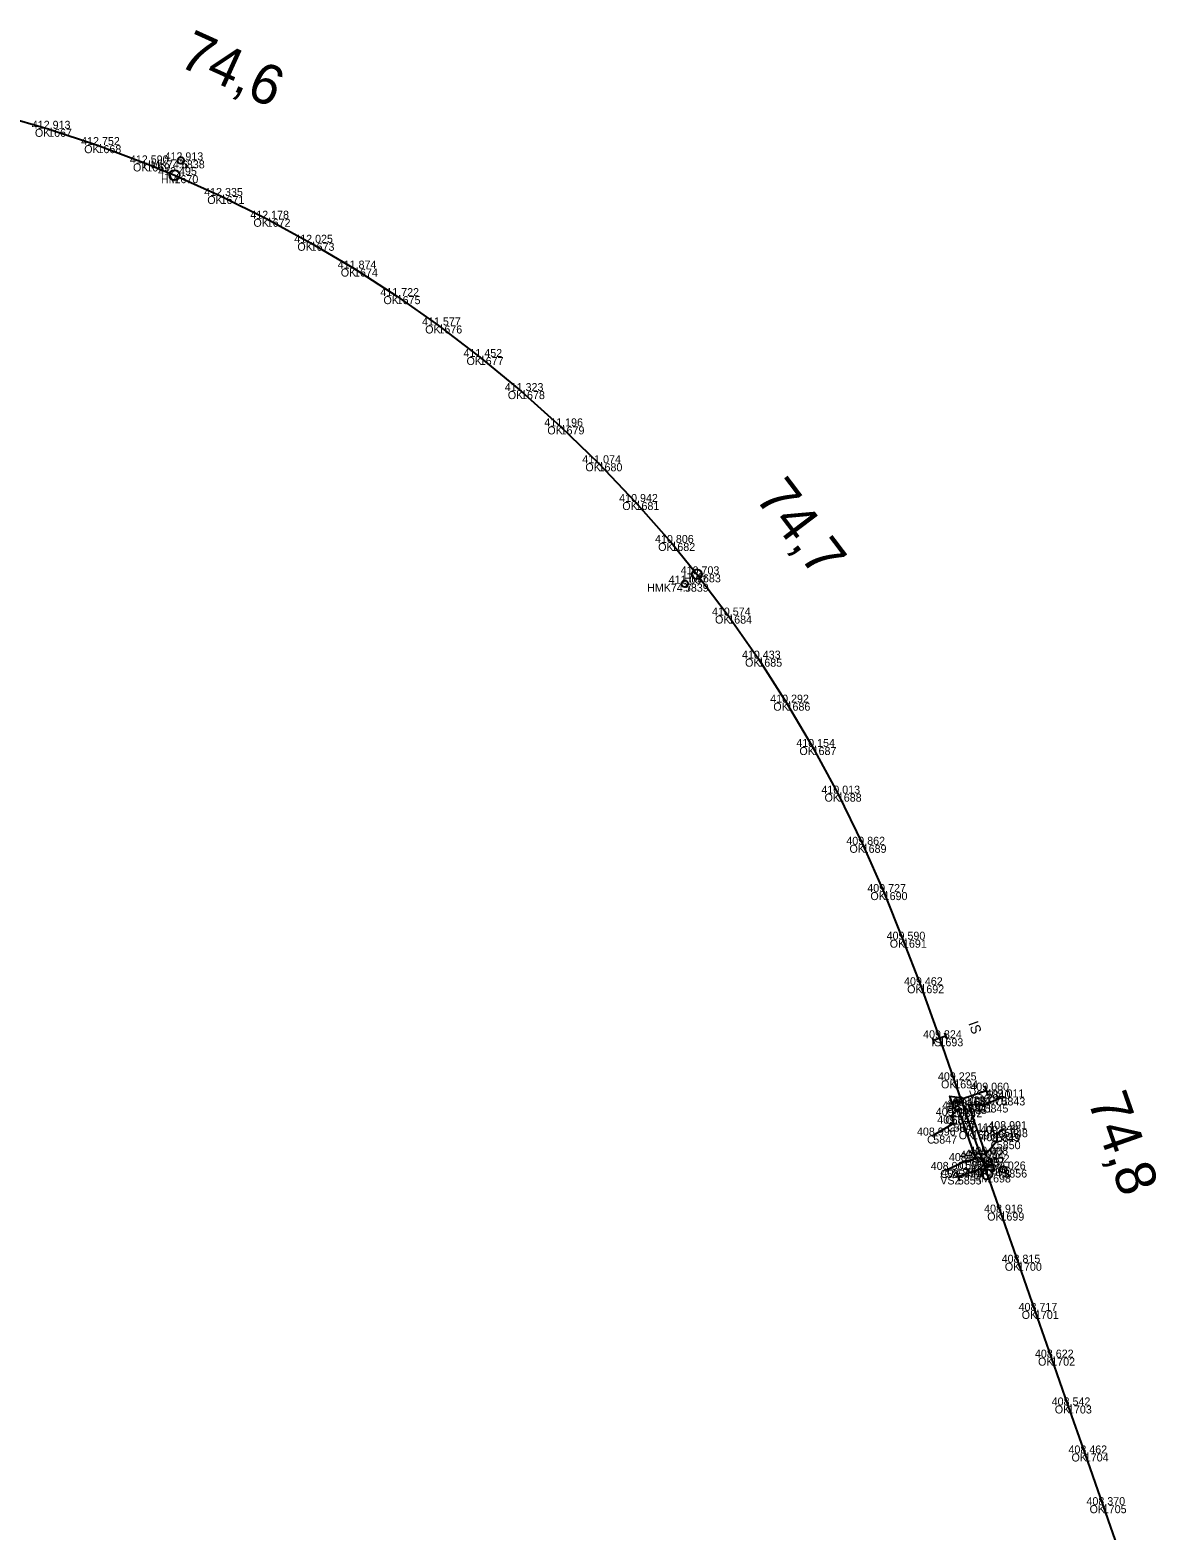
# Model space of a CAD drawing. Extents: x -621782 to -610392, y -1141853 to -1122321.
# Drawn here: x -619167.3 to -618998.3, y -1130303.7 to -1130078.8 of the extents above; entities that cross this region are included whole.
import ezdxf

# ---------------------------------------------------------------- set-up
doc = ezdxf.new("R2010")
doc.units = 0
for name, color, linetype in [('Vrstva 1', 7, 'Continuous'), ('Vrstva 3', 7, 'Continuous'), ('Vrstva 4', 7, 'Continuous'), ('Vrstva 51', 7, 'Continuous'), ('Vrstva 60', 7, 'Continuous'), ('Vrstva 61', 7, 'Continuous'), ('Vrstva 62', 7, 'Continuous'), ('Vrstva 7', 7, 'Continuous')]:
    doc.layers.add(name, color=color, linetype=linetype)

msp = doc.modelspace()

# ---------------------------------------------------------------- linework, layer by layer
at = {"layer": 'Vrstva 1'}
msp.add_lwpolyline([(-619171.08, -1130091.68), (-619164.55, -1130093.59), (-619157.15, -1130096.03), (-619149.84, -1130098.78), (-619145.6, -1130100.54), (-619138.69, -1130103.66), (-619131.77, -1130107.08), (-619125.18, -1130110.68), (-619118.67, -1130114.55), (-619112.28, -1130118.68), (-619106.02, -1130123.08), (-619099.82, -1130127.81), (-619093.62, -1130132.92), (-619087.69, -1130138.21), (-619082, -1130143.74), (-619076.46, -1130149.55), (-619071.08, -1130155.69), (-619067.24, -1130160.39), (-619062.55, -1130166.58), (-619058.04, -1130173.04), (-619053.81, -1130179.64), (-619049.9, -1130186.28), (-619046.12, -1130193.28), (-619042.39, -1130200.95), (-619039.24, -1130208.04), (-619036.35, -1130215.18), (-619033.74, -1130222.01), (-619030.88, -1130229.96), (-619028.66, -1130236.27), (-619027.33, -1130240.12), (-619026.01, -1130243.9), (-619024.61, -1130247.86), (-619023.73, -1130250.38), (-619021.73, -1130256.1), (-619019.09, -1130263.62), (-619016.56, -1130270.84), (-619014.11, -1130277.85), (-619011.6, -1130285.02), (-619009.08, -1130292.22), (-619006.38, -1130299.97), (-619003.78, -1130307.42)], dxfattribs=at)
at = {"layer": 'Vrstva 3'}
for p, q in [((-619030.11, -1130229.15), (-619029.77, -1130230.09)), ((-619031.99, -1130229.82), (-619031.65, -1130230.77)), ((-619029.94, -1130229.62), (-619031.82, -1130230.3))]:
    msp.add_line(p, q, dxfattribs=at)
at = {"layer": 'Vrstva 4'}
for p, q in [((-619023.55, -1130238.56), (-619024.05, -1130237.09)), ((-619028.15, -1130239.54), (-619028.58, -1130239.32)), ((-619023.78, -1130248.94), (-619023.34, -1130249.15)), ((-619028.37, -1130249.94), (-619027.86, -1130251.41))]:
    msp.add_line(p, q, dxfattribs=at)
for points in [[(-619023.8, -1130237.82), (-619027.09, -1130238.96), (-619028.66, -1130240.54), (-619029.32, -1130238.66), (-619027.09, -1130238.96)], [(-619027.33, -1130240.12), (-619026.01, -1130243.9), (-619024.61, -1130247.86)], [(-619028.12, -1130250.68), (-619024.83, -1130249.53), (-619023.27, -1130247.93), (-619022.6, -1130249.82), (-619024.83, -1130249.53)]]:
    msp.add_lwpolyline(points, dxfattribs=at)
for centre in [(-619028.36, -1130239.43), (-619023.56, -1130249.05)]:
    msp.add_circle(centre, 0.248, dxfattribs=at)
at = {"layer": 'Vrstva 51'}
for points in [[(-619029.82, -1130249.7), (-619027.01, -1130248.38), (-619025.42, -1130248.01), (-619028.02, -1130240.61), (-619029.07, -1130241.58), (-619028.76, -1130242.76), (-619031.8, -1130244.55)], [(-619021.19, -1130243.59), (-619022.32, -1130244.28), (-619022.28, -1130245.39), (-619023.94, -1130247.41), (-619026.54, -1130239.87), (-619024.11, -1130239.89), (-619021.58, -1130238.83)]]:
    msp.add_lwpolyline(points, dxfattribs=at)
at = {"layer": 'Vrstva 60'}
for p, q in [((-619164.55, -1130093.59), (-619164.55, -1130093.59)), ((-619157.15, -1130096.03), (-619157.15, -1130096.03)), ((-619149.84, -1130098.78), (-619149.84, -1130098.78)), ((-619144.64, -1130098.32), (-619144.64, -1130098.32)), ((-619145.6, -1130100.54), (-619145.6, -1130100.54)), ((-619138.69, -1130103.66), (-619138.69, -1130103.66)), ((-619131.77, -1130107.08), (-619131.77, -1130107.08)), ((-619125.18, -1130110.68), (-619125.18, -1130110.68)), ((-619118.67, -1130114.55), (-619118.67, -1130114.55)), ((-619112.28, -1130118.68), (-619112.28, -1130118.68)), ((-619106.02, -1130123.08), (-619106.02, -1130123.08)), ((-619099.82, -1130127.81), (-619099.82, -1130127.81)), ((-619093.62, -1130132.92), (-619093.62, -1130132.92)), ((-619087.69, -1130138.21), (-619087.69, -1130138.21)), ((-619082, -1130143.74), (-619082, -1130143.74)), ((-619076.46, -1130149.55), (-619076.46, -1130149.55)), ((-619071.08, -1130155.69), (-619071.08, -1130155.69)), ((-619069.05, -1130161.8), (-619069.05, -1130161.8)), ((-619067.24, -1130160.39), (-619067.24, -1130160.39)), ((-619062.55, -1130166.58), (-619062.55, -1130166.58)), ((-619058.04, -1130173.04), (-619058.04, -1130173.04)), ((-619053.81, -1130179.64), (-619053.81, -1130179.64)), ((-619049.9, -1130186.28), (-619049.9, -1130186.28)), ((-619046.12, -1130193.28), (-619046.12, -1130193.28)), ((-619042.39, -1130200.95), (-619042.39, -1130200.95)), ((-619039.24, -1130208.04), (-619039.24, -1130208.04)), ((-619036.35, -1130215.18), (-619036.35, -1130215.18)), ((-619033.74, -1130222.01), (-619033.74, -1130222.01)), ((-619030.88, -1130229.96), (-619030.88, -1130229.96)), ((-619028.66, -1130236.27), (-619028.66, -1130236.27)), ((-619023.8, -1130237.82), (-619023.8, -1130237.82)), ((-619028.02, -1130240.61), (-619028.02, -1130240.61)), ((-619027.33, -1130240.12), (-619027.33, -1130240.12)), ((-619026.54, -1130239.87), (-619026.54, -1130239.87)), ((-619024.11, -1130239.89), (-619024.11, -1130239.89)), ((-619021.58, -1130238.83), (-619021.58, -1130238.83)), ((-619029.07, -1130241.58), (-619029.07, -1130241.58)), ((-619028.76, -1130242.76), (-619028.76, -1130242.76)), ((-619031.8, -1130244.55), (-619031.8, -1130244.55)), ((-619026.01, -1130243.9), (-619026.01, -1130243.9)), ((-619022.32, -1130244.28), (-619022.32, -1130244.28)), ((-619021.19, -1130243.59), (-619021.19, -1130243.59)), ((-619023.94, -1130247.41), (-619023.94, -1130247.41)), ((-619022.28, -1130245.39), (-619022.28, -1130245.39)), ((-619027.01, -1130248.38), (-619027.01, -1130248.38)), ((-619025.42, -1130248.01), (-619025.42, -1130248.01)), ((-619024.61, -1130247.86), (-619024.61, -1130247.86)), ((-619021.3, -1130249.64), (-619021.3, -1130249.64)), ((-619029.82, -1130249.7), (-619029.82, -1130249.7)), ((-619028.12, -1130250.68), (-619028.12, -1130250.68)), ((-619023.73, -1130250.38), (-619023.73, -1130250.38)), ((-619021.73, -1130256.1), (-619021.73, -1130256.1)), ((-619019.09, -1130263.62), (-619019.09, -1130263.62)), ((-619016.56, -1130270.84), (-619016.56, -1130270.84)), ((-619014.11, -1130277.85), (-619014.11, -1130277.85)), ((-619011.6, -1130285.02), (-619011.6, -1130285.02)), ((-619009.08, -1130292.22), (-619009.08, -1130292.22)), ((-619006.38, -1130299.97), (-619006.38, -1130299.97))]:
    msp.add_line(p, q, dxfattribs=at)
at = {"layer": 'Vrstva 7'}
for p, q in [((-619144.69, -1130098.3), (-619144.59, -1130098.34)), ((-619069.08, -1130161.76), (-619069.02, -1130161.84)), ((-619021.32, -1130249.6), (-619021.29, -1130249.69))]:
    msp.add_line(p, q, dxfattribs=at)
for centre, radius in [((-619144.64, -1130098.32), 0.5), ((-619145.6, -1130100.54), 0.75), ((-619067.24, -1130160.39), 0.75), ((-619069.05, -1130161.8), 0.5), ((-619023.73, -1130250.38), 0.75), ((-619021.3, -1130249.64), 0.5)]:
    msp.add_circle(centre, radius, dxfattribs=at)

# ---------------------------------------------------------------- texts
at = {"layer": 'Vrstva 3'}
msp.add_text('IS', height=1.5, rotation=289.7838, dxfattribs=at).set_placement((-619026.56, -1130227.7))
at = {"layer": 'Vrstva 60'}
for s, p in [('1667', (-619164.55, -1130094.79)), ('1668', (-619157.15, -1130097.24)), ('1669', (-619149.84, -1130099.98)), ('5838', (-619144.64, -1130099.52)), ('1670', (-619145.6, -1130101.74)), ('1671', (-619138.69, -1130104.86)), ('1672', (-619131.77, -1130108.28)), ('1673', (-619125.18, -1130111.88)), ('1674', (-619118.67, -1130115.75)), ('1675', (-619112.28, -1130119.88)), ('1676', (-619106.02, -1130124.28)), ('1677', (-619099.82, -1130129.01)), ('1678', (-619093.62, -1130134.12)), ('1679', (-619087.69, -1130139.41)), ('1680', (-619082, -1130144.94)), ('1681', (-619076.46, -1130150.75)), ('1682', (-619071.08, -1130156.89)), ('5839', (-619069.05, -1130163)), ('1683', (-619067.24, -1130161.59)), ('1684', (-619062.55, -1130167.78)), ('1685', (-619058.04, -1130174.24)), ('1686', (-619053.81, -1130180.84)), ('1687', (-619049.9, -1130187.49)), ('1688', (-619046.12, -1130194.48)), ('1689', (-619042.39, -1130202.15)), ('1690', (-619039.24, -1130209.24)), ('1691', (-619036.35, -1130216.38)), ('1692', (-619033.74, -1130223.21)), ('1693', (-619030.88, -1130231.16)), ('1694', (-619028.66, -1130237.47)), ('5840', (-619023.8, -1130239.02)), ('5842', (-619028.02, -1130241.81)), ('1695', (-619027.33, -1130241.32)), ('5841', (-619026.54, -1130241.07)), ('5845', (-619024.11, -1130241.09)), ('5843', (-619021.58, -1130240.03)), ('5844', (-619029.07, -1130242.78)), ('5846', (-619028.76, -1130243.96)), ('5847', (-619031.8, -1130245.75)), ('1696', (-619026.01, -1130245.1)), ('5849', (-619022.32, -1130245.48)), ('5848', (-619021.19, -1130244.79)), ('5852', (-619023.94, -1130248.6)), ('5850', (-619022.28, -1130246.59)), ('5851', (-619027.01, -1130249.58)), ('5853', (-619025.42, -1130249.21)), ('1697', (-619024.61, -1130249.06)), ('5856', (-619021.3, -1130250.84)), ('5854', (-619029.82, -1130250.9)), ('5855', (-619028.12, -1130251.88)), ('1698', (-619023.73, -1130251.58)), ('1699', (-619021.73, -1130257.3)), ('1700', (-619019.09, -1130264.82)), ('1701', (-619016.56, -1130272.04)), ('1702', (-619014.11, -1130279.05)), ('1703', (-619011.6, -1130286.22)), ('1704', (-619009.08, -1130293.42)), ('1705', (-619006.38, -1130301.17))]:
    msp.add_text(s, height=1.2, dxfattribs=at).set_placement(p)
at = {"layer": 'Vrstva 61'}
for s, p in [('412.913', (-619167, -1130093.59)), ('412.752', (-619159.6, -1130096.03)), ('412.590', (-619152.29, -1130098.78)), ('412.913', (-619147.09, -1130098.32)), ('412.495', (-619148.05, -1130100.54)), ('412.335', (-619141.15, -1130103.66)), ('412.178', (-619134.23, -1130107.08)), ('412.025', (-619127.64, -1130110.68)), ('411.874', (-619121.12, -1130114.55)), ('411.722', (-619114.73, -1130118.68)), ('411.577', (-619108.47, -1130123.08)), ('411.452', (-619102.26, -1130127.81)), ('411.323', (-619096.07, -1130132.92)), ('411.196', (-619090.14, -1130138.21)), ('411.074', (-619084.45, -1130143.74)), ('410.942', (-619078.91, -1130149.55)), ('410.806', (-619073.53, -1130155.69)), ('410.703', (-619069.69, -1130160.39)), ('411.057', (-619071.5, -1130161.8)), ('410.574', (-619065, -1130166.58)), ('410.433', (-619060.5, -1130173.04)), ('410.292', (-619056.26, -1130179.64)), ('410.154', (-619052.35, -1130186.28)), ('410.013', (-619048.58, -1130193.28)), ('409.862', (-619044.84, -1130200.95)), ('409.727', (-619041.7, -1130208.04)), ('409.590', (-619038.8, -1130215.18)), ('409.462', (-619036.19, -1130222.01)), ('409.324', (-619033.33, -1130229.96)), ('409.225', (-619031.11, -1130236.27)), ('409.060', (-619026.25, -1130237.82)), ('409.011', (-619023.94, -1130238.83)), ('409.001', (-619031.43, -1130241.58)), ('409.118', (-619030.47, -1130240.61)), ('409.168', (-619029.78, -1130240.12)), ('409.134', (-619028.99, -1130239.87)), ('409.070', (-619026.57, -1130239.89)), ('409.056', (-619031.21, -1130242.76)), ('409.111', (-619028.36, -1130243.9)), ('408.991', (-619023.55, -1130243.59)), ('408.996', (-619034.25, -1130244.55)), ('409.038', (-619024.77, -1130244.28)), ('409.033', (-619024.73, -1130245.39)), ('408.992', (-619029.46, -1130248.38)), ('409.021', (-619027.78, -1130248.01)), ('409.052', (-619027.06, -1130247.86)), ('409.008', (-619026.39, -1130247.41)), ('408.901', (-619032.18, -1130249.7)), ('408.894', (-619030.57, -1130250.68)), ('409.006', (-619026.18, -1130250.38)), ('409.026', (-619023.75, -1130249.64)), ('408.916', (-619024.18, -1130256.1)), ('408.815', (-619021.55, -1130263.62)), ('408.717', (-619019.01, -1130270.84)), ('408.622', (-619016.56, -1130277.85)), ('408.542', (-619014.05, -1130285.02)), ('408.462', (-619011.53, -1130292.22)), ('408.370', (-619008.83, -1130299.97))]:
    msp.add_text(s, height=1.2, dxfattribs=at).set_placement(p)
at = {"layer": 'Vrstva 62'}
for s, p in [('OK', (-619166.53, -1130094.79)), ('OK', (-619159.14, -1130097.24)), ('OK', (-619151.82, -1130099.98)), ('HMK74.6', (-619150.3, -1130099.52)), ('HM', (-619147.63, -1130101.74)), ('OK', (-619140.68, -1130104.86)), ('OK', (-619133.76, -1130108.28)), ('OK', (-619127.17, -1130111.88)), ('OK', (-619120.66, -1130115.75)), ('OK', (-619114.26, -1130119.88)), ('OK', (-619108, -1130124.28)), ('OK', (-619101.8, -1130129.01)), ('OK', (-619095.61, -1130134.12)), ('OK', (-619089.68, -1130139.41)), ('OK', (-619083.98, -1130144.94)), ('OK', (-619078.44, -1130150.75)), ('OK', (-619073.06, -1130156.89)), ('HMK74.7', (-619074.72, -1130163)), ('HM', (-619069.27, -1130161.59)), ('OK', (-619064.53, -1130167.78)), ('OK', (-619060.03, -1130174.24)), ('OK', (-619055.79, -1130180.84)), ('OK', (-619051.88, -1130187.49)), ('OK', (-619048.11, -1130194.48)), ('OK', (-619044.37, -1130202.15)), ('OK', (-619041.23, -1130209.24)), ('OK', (-619038.33, -1130216.38)), ('OK', (-619035.72, -1130223.21)), ('IS', (-619032.11, -1130231.16)), ('OK', (-619030.64, -1130237.47)), ('VSZ', (-619026.44, -1130239.02)), ('PRJ', (-619029.81, -1130241.32)), ('C', (-619028.95, -1130241.81)), ('C', (-619027.47, -1130241.07)), ('C', (-619025.05, -1130241.09)), ('C', (-619022.52, -1130240.03)), ('C', (-619030.01, -1130242.78)), ('C', (-619029.69, -1130243.96)), ('C', (-619032.73, -1130245.75)), ('OK', (-619027.99, -1130245.1)), ('C', (-619023.25, -1130245.48)), ('C', (-619022.12, -1130244.79)), ('C', (-619024.87, -1130248.6)), ('C', (-619023.21, -1130246.59)), ('C', (-619027.95, -1130249.58)), ('PRJ', (-619027.1, -1130249.06)), ('HMK74.8', (-619026.97, -1130250.84)), ('C', (-619026.36, -1130249.21)), ('VSZ', (-619030.76, -1130251.88)), ('C', (-619030.76, -1130250.9)), ('HM', (-619025.76, -1130251.58)), ('OK', (-619023.71, -1130257.3)), ('OK', (-619021.07, -1130264.82)), ('OK', (-619018.54, -1130272.04)), ('OK', (-619016.09, -1130279.05)), ('OK', (-619013.58, -1130286.22)), ('OK', (-619011.07, -1130293.42)), ('OK', (-619008.36, -1130301.17))]:
    msp.add_text(s, height=1.2, dxfattribs=at).set_placement(p)
at = {"layer": 'Vrstva 7'}
for s, rotation, p in [('74,6', 335.6774, (-619145.22, -1130084.07)), ('74,7', 307.1381, (-619058.68, -1130148.9)), ('74,8', 289.2972, (-619008.69, -1130239.25))]:
    msp.add_text(s, height=6, rotation=rotation, dxfattribs=at).set_placement(p)

doc.saveas('drawing.dxf')
